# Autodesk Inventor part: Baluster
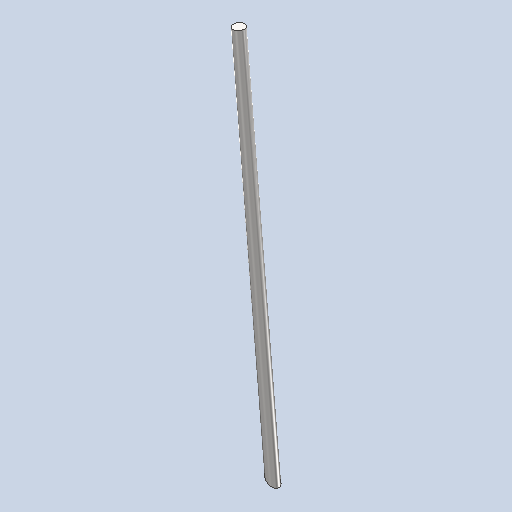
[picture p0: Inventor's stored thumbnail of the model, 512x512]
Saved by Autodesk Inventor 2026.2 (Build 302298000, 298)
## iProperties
Created: 2022-06
Part Number: Baluster
Material: Steel, Galvanized
Document SubType Name: Modeling
Designer: reaumed
Density: 7.85 g/cm^3
Appearance: Galvanized
Mass: 3323.97 g
Surface Area: 678.138 cm^2
Volume: 423.435 cm^3
Author: reaumed
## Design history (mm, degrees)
workplane "Work Plane1"
workplane "Work Plane2"
workplane "Work Plane3"
sketch "Sketch1"
  geometry: L1 (-1249.535, 361.95)-(1728.542, 361.95) reference; L2 (114.3, 632.46)-(114.3, -105.41) reference; C1 r 12.7 at (114.3, 361.95); 1 further point
  constraints: 1 centre point
  dimensions: "d3" = 0 distance from line of C1.centre L1; "d4" = 0 distance from line of L2 C1.centre; "d7" = 25.4 diameter of C1 (= BalusterDia)
extrude "Extrusion1" new body sketch "Sketch1" distance "d5" = 927.1 (= BalusterLength + 0.5 x BalusterDia); taper "d6" = 0 deg
sketch "Sketch2"
  geometry: L1 (-228.6, -190.5)-(-1353.565, -1127.971); L2 (0, -190.5)-(-228.6, -190.5); L3 (773.632, -1127.971)-(-1353.565, -1127.971); 1 further point
  constraints: 6 end point, 2 horizontal
  dimensions: "d8" = 190.5 distance from line of L2 point (0, 0) (= Rise); "d9" = 228.6 horizontal distance of L1.start point (0, 0) (= Run); "d10" = 39.8056 deg angle of L3 L1 (= TheAngle)
workplane "Work Plane7"
split "Split4"
body "Solid1"
other parameters: "Rise" = 190.5 [user parameter; used in 2 equation terms], "Run" = 228.6 [user parameter; used in 2 equation terms], "Width" = 762 [user parameter; used in 1 equation term], "d0" = -190.5 (= -Rise), "d1" = 361.95 (= 0.5 x Width - 0.5 x StringerThickness), "d2" = 114.3 (= 0.5 x Run), "BalusterDia" = 25.4 [user parameter; used in 2 equation terms], "BalusterLength" = 914.4 [user parameter; used in 1 equation term], "StringerThickness" = 38.1 [user parameter; used in 1 equation term], "TreadThickness" = 31.75 [user parameter], "d11" = 90 deg, "TheAngle" = 39.8056 deg [user parameter; used in 1 equation term]
